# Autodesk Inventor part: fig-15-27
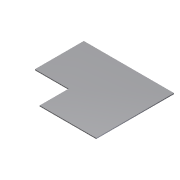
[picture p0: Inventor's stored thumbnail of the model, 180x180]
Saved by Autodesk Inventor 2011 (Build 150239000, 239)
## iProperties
Created: 2005-03
Part Number: fig-15-27
Document SubType Name: Sheet Metal
Designer: CADCIM
Manufacturer: Standard
Standards Organization: Custom
Density: 1 g/cm^3
Sheet Metal Rule: Default
Author: CADCIM
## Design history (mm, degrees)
node "Face1"
  sketch "Sketch1"
    geometry: L1 (29.25, 32.25)-(-19.875, 32.25); L2 (-19.875, 32.25)-(-19.875, 5.625); L3 (-19.875, 5.625)-(-1.5, 5.625); L4 (-1.5, 5.625)-(-1.5, -10.125); L5 (-1.5, -10.125)-(29.25, -10.125); L6 (29.25, -10.125)-(29.25, 32.25)
    constraints: 12 end point, 4 parallel, 1 horizontal, 1 perpendicular
body "Solid1"
face "Plate1" dims "Thickness" = 0.5
other parameters: "BendRadius" = 0.5 (= Thickness), "BendReliefWidth" = 0.5 (= Thickness), "BendReliefDepth" = 0.25 (= 0.5 x Thickness), "CornerReliefSize" = 2 (= 4 x Thickness), "SeamGap" = 0.01, "MinimumRemnant" = 1 (= 2 x Thickness), "TransitionRadius" = 0.5 (= BendRadius), "JacobiRadiusSize" = 0.5 (= Thickness), "GapSize" = 0.5 (= Thickness), "d0" = 0.5 (= BendRadius)
